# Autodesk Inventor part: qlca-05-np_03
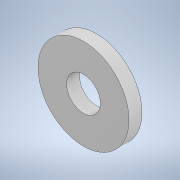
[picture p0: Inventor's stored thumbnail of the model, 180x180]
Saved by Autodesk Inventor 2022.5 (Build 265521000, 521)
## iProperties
Created: 2023-06
Part Number: qlca-05-np_03
Material: Generic
Document SubType Name: Modeling
Designer: ImaoCorp
Density: 1 g/cm^3
Appearance: Default
Author: ImaoCorp
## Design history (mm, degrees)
feature "qlca-05-np_03"
node "ソリッド1"
